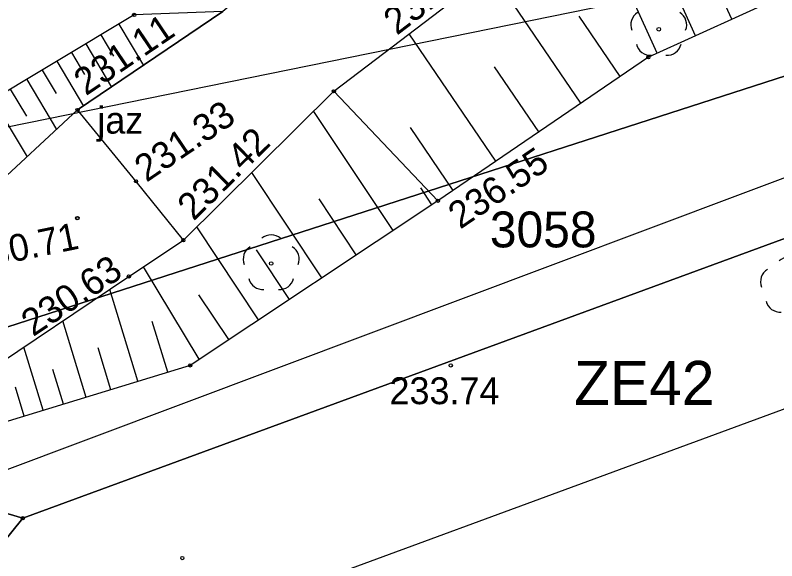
# Model space of a CAD drawing. Extents: x 6596400 to 6597200, y 5539751 to 5540251.
# Drawn here: x 6596752.84 to 6596774.08, y 5540046.04 to 5540061.24 of the extents above; entities that cross this region are included whole.
import ezdxf

# ---------------------------------------------------------------- set-up
doc = ezdxf.new("R2010")
doc.units = 0
for name, color, linetype in [('000 Inne (niezydentyfikowane)', 7, 'Continuous'), ('140-Punkty robocze', 7, 'Continuous'), ('203-punkt graniczny', 7, 'Continuous'), ('211-numer działki ewidencyjnej', 7, 'Continuous'), ('217-kontur klasyfikacyjny', 7, 'Continuous'), ('218-kontur użytku gruntowego', 7, 'Continuous'), ('219-działka ewidencyjna', 7, 'Continuous'), ('drzewo liściaste', 7, 'Continuous'), ('jaz', 7, 'Continuous'), ('jaz-Atr17', 7, 'Continuous'), ('Linia obszaru zagospodarowania terenu', 7, 'Continuous'), ('Opis obszaru zagospodarowania terenu', 7, 'Continuous'), ('pikieta sztuczna', 7, 'Continuous'), ('pikieta sztuczna-Atr2', 7, 'Continuous'), ('rów melioracyjny (poligon)', 7, 'Continuous'), ('skarpa nieumocniona', 7, 'Continuous'), ('skarpa umocniona', 7, 'Continuous'), ('Zakres', 7, 'Continuous')]:
    doc.layers.add(name, color=color, linetype=linetype)

# ---------------------------------------------------------------- blocks, each defined once
blk = doc.blocks.new('203')
blk.add_circle((0, 0), 0.045)
blk = doc.blocks.new('OP021')
blk.add_circle((0, 0), 0.05)
for centre, start, end in [((0, 0.4), 49.272, 130.728), ((-0.38, 0.124), 121.308, 202.548), ((0.38, 0.124), 337.452, 58.692), ((-0.235, -0.324), 193.221, 274.871), ((0.235, -0.324), 265.129, 346.779)]:
    blk.add_arc(centre, 0.4, start, end)
blk = doc.blocks.new('PIKIETA')
blk.add_circle((0, 0), 0.045)
blk = doc.blocks.new('PW01')
blk.add_circle((0, 0), 0.045)

msp = doc.modelspace()

# ---------------------------------------------------------------- linework, layer by layer
at = {"layer": '000 Inne (niezydentyfikowane)'}
for p, q in [((6596772.83, 5540061.13), (6596771.44, 5540064.19)), ((6596770.75, 5540060.18), (6596769.2, 5540063.59)), ((6596768.62, 5540058.79), (6596766.16, 5540062.4)), ((6596771.82, 5540060.67), (6596771.08, 5540062.29)), ((6596769.71, 5540059.53), (6596768.57, 5540061.21)), ((6596766.25, 5540057.17), (6596763.83, 5540060.72)), ((6596767.45, 5540057.99), (6596766.21, 5540059.8)), ((6596763.38, 5540055.24), (6596761.17, 5540058.56)), ((6596765.06, 5540056.36), (6596763.87, 5540058.11)), ((6596761.39, 5540053.92), (6596759.44, 5540056.86)), ((6596764.46, 5540055.96), (6596764.15, 5540056.43)), ((6596762.35, 5540054.56), (6596761.32, 5540056.12)), ((6596759.63, 5540052.75), (6596757.91, 5540055.34)), ((6596760.49, 5540053.32), (6596759.57, 5540054.7)), ((6596757.97, 5540051.65), (6596756.42, 5540054.23)), ((6596756.26, 5540051.04), (6596755.48, 5540053.6)), ((6596758.8, 5540052.2), (6596757.96, 5540053.45)), ((6596754.82, 5540050.59), (6596754.17, 5540052.72)), ((6596757.1, 5540051.29), (6596756.66, 5540052.7)), ((6596753.62, 5540050.23), (6596753.08, 5540051.99)), ((6596755.51, 5540050.8), (6596755.15, 5540051.97)), ((6596754.19, 5540050.4), (6596753.89, 5540051.37)), ((6596753.09, 5540050.07), (6596752.85, 5540050.87))]:
    msp.add_line(p, q, dxfattribs=at)
for points in [[(6596755.73, 5540060.99), (6596756.42, 5540059.84)], [(6596755.23, 5540060.69), (6596755.58, 5540060.1)], [(6596754.81, 5540060.44), (6596755.53, 5540059.24)], [(6596754.41, 5540060.2), (6596754.77, 5540059.59)], [(6596754, 5540059.96), (6596754.74, 5540058.71)], [(6596753.59, 5540059.71), (6596753.98, 5540059.06)], [(6596753.16, 5540059.45), (6596753.99, 5540058.06)], [(6596752.7, 5540059.18), (6596753.15, 5540058.43)], [(6596752.21, 5540058.89), (6596753.17, 5540057.29)]]:
    msp.add_lwpolyline(points, dxfattribs=at)
at = {"layer": '217-kontur klasyfikacyjny'}
for points in [[(6596787.06, 5540059.7), (6596753.05, 5540047.22)], [(6596753.05, 5540047.22), (6596750.47, 5540044.03)]]:
    msp.add_lwpolyline(points, dxfattribs=at)
at = {"layer": '218-kontur użytku gruntowego'}
for points in [[(6596786.08, 5540063.35), (6596749.37, 5540051.51)], [(6596749.37, 5540051.51), (6596786.08, 5540063.35)], [(6596787.06, 5540059.7), (6596753.05, 5540047.22)], [(6596753.05, 5540047.22), (6596787.06, 5540059.7)], [(6596732.94, 5540053.15), (6596753.05, 5540047.22)], [(6596753.05, 5540047.22), (6596732.94, 5540053.15)], [(6596753.05, 5540047.22), (6596750.47, 5540044.03)], [(6596750.47, 5540044.03), (6596753.05, 5540047.22)]]:
    msp.add_lwpolyline(points, dxfattribs=at)
at = {"layer": '219-działka ewidencyjna'}
for points in [[(6596749.37, 5540051.51), (6596786.08, 5540063.35)], [(6596753.05, 5540047.22), (6596787.06, 5540059.7)], [(6596753.05, 5540047.22), (6596732.94, 5540053.15)], [(6596750.47, 5540044.03), (6596753.05, 5540047.22)]]:
    msp.add_lwpolyline(points, dxfattribs=at)
at = {"layer": 'jaz'}
msp.add_lwpolyline([(6596757.53, 5540054.97), (6596756.21, 5540056.61), (6596754.58, 5540058.6)], dxfattribs=at)
at = {"layer": 'Linia obszaru zagospodarowania terenu'}
for points in [[(6596720.263, 5540058.387), (6596728.96, 5540057.84), (6596731.45, 5540057.76), (6596731.02, 5540064.64), (6596745.49, 5540064.58), (6596746.99, 5540056.99), (6596772.84, 5540062.25), (6596786.21, 5540064.83), (6596807.99, 5540057.58), (6596818.837, 5540049.192)], [(6596816.371, 5540045.853), (6596805.78, 5540054.39), (6596786.09, 5540061.13), (6596752.3, 5540048.46), (6596750.16, 5540045.43), (6596750.4, 5540037.69), (6596745.15, 5540037.73), (6596747.098, 5540030.366)]]:
    msp.add_lwpolyline(points, dxfattribs=at)
at = {"layer": 'rów melioracyjny (poligon)'}
for points in [[(6596820.208, 5540051.05), (6596817.24, 5540053.08), (6596812.31, 5540056.77), (6596808.36, 5540059.4), (6596802.55, 5540062.58), (6596795.13, 5540065.25), (6596788.99, 5540067.23), (6596782.3, 5540068.04), (6596775.52, 5540068.1), (6596768.51, 5540067.33), (6596764.82, 5540065.79), (6596761.35, 5540063.62), (6596758.63, 5540061.34), (6596754.58, 5540058.6), (6596752.07, 5540056.28), (6596746.75, 5540055.19), (6596741.65, 5540054.82), (6596742.01, 5540050.53), (6596747.46, 5540050.98), (6596751.88, 5540051.19), (6596756.01, 5540053.96), (6596757.53, 5540054.97), (6596761.73, 5540059.12)], [(6596761.73, 5540059.12), (6596765.87, 5540062.28), (6596769.5, 5540063.71), (6596775.27, 5540065.15), (6596782.49, 5540064.38), (6596788.18, 5540063.76), (6596793.92, 5540062.6), (6596807.97, 5540055.99), (6596815, 5540051.7), (6596818.611, 5540048.887)]]:
    msp.add_lwpolyline(points, dxfattribs=at)
at = {"layer": 'skarpa nieumocniona'}
for points in [[(6596756.16, 5540061.25), (6596751.77, 5540058.62), (6596746.79, 5540058.12), (6596745.06, 5540060.97), (6596743.75, 5540062.98), (6596744.34, 5540066.61), (6596742.94, 5540074), (6596740.68, 5540078.45), (6596741.68, 5540074.92), (6596743.25, 5540066.3), (6596742.47, 5540061.97), (6596741.65, 5540054.82), (6596746.75, 5540055.19), (6596752.07, 5540056.28), (6596754.58, 5540058.6), (6596758.63, 5540061.34)], [(6596756.16, 5540061.25), (6596751.77, 5540058.62), (6596746.79, 5540058.12), (6596745.06, 5540060.97), (6596743.75, 5540062.98), (6596744.34, 5540066.61), (6596742.94, 5540074), (6596740.68, 5540078.45), (6596741.68, 5540074.92), (6596743.25, 5540066.3), (6596742.47, 5540061.97), (6596741.65, 5540054.82), (6596746.75, 5540055.19), (6596752.07, 5540056.28), (6596754.58, 5540058.6), (6596758.63, 5540061.34)], [(6596764.63, 5540056.07), (6596757.72, 5540051.48), (6596748.68, 5540048.72), (6596744.91, 5540048.46), (6596747.72, 5540041.03), (6596748.61, 5540037.56), (6596751.13, 5540029.81), (6596749.69, 5540030.01), (6596747.71, 5540037.43), (6596746.88, 5540041.11), (6596746.88, 5540042.02), (6596743.2, 5540046.89), (6596742.01, 5540050.53), (6596747.46, 5540050.98), (6596751.88, 5540051.19), (6596756.01, 5540053.96), (6596757.53, 5540054.97), (6596761.73, 5540059.12)], [(6596764.63, 5540056.07), (6596757.72, 5540051.48), (6596748.68, 5540048.72), (6596744.91, 5540048.46), (6596747.72, 5540041.03), (6596748.61, 5540037.56), (6596751.13, 5540029.81), (6596749.69, 5540030.01), (6596747.71, 5540037.43), (6596746.88, 5540041.11), (6596746.88, 5540042.02), (6596743.2, 5540046.89), (6596742.01, 5540050.53), (6596747.46, 5540050.98), (6596751.88, 5540051.19), (6596756.01, 5540053.96), (6596757.53, 5540054.97), (6596761.73, 5540059.12)]]:
    msp.add_lwpolyline(points, close=True, dxfattribs=at)
at = {"layer": 'skarpa umocniona'}
msp.add_lwpolyline([(6596782.49, 5540064.38), (6596788.18, 5540063.76), (6596793.92, 5540062.6), (6596807.97, 5540055.99), (6596815, 5540051.7), (6596818.61, 5540048.89), (6596817.09, 5540046.82), (6596813.04, 5540049.86), (6596807.32, 5540053.71), (6596801, 5540055.88), (6596793.16, 5540059.3), (6596788.6, 5540060.8), (6596783.73, 5540060.81), (6596779.28, 5540061), (6596774.44, 5540061.86), (6596770.5, 5540060.07), (6596764.63, 5540056.07), (6596761.73, 5540059.12), (6596765.87, 5540062.28), (6596769.5, 5540063.71), (6596775.27, 5540065.15)], close=True, dxfattribs=at)
msp.add_lwpolyline([(6596782.49, 5540064.38), (6596788.18, 5540063.76), (6596793.92, 5540062.6), (6596807.97, 5540055.99), (6596815, 5540051.7), (6596818.61, 5540048.89), (6596817.09, 5540046.82), (6596813.04, 5540049.86), (6596807.32, 5540053.71), (6596801, 5540055.88), (6596793.16, 5540059.3), (6596788.6, 5540060.8), (6596783.73, 5540060.81), (6596779.28, 5540061), (6596774.44, 5540061.86), (6596770.5, 5540060.07), (6596764.63, 5540056.07), (6596761.73, 5540059.12), (6596765.87, 5540062.28), (6596769.5, 5540063.71), (6596775.27, 5540065.15)], close=True, dxfattribs=at)
at = {"layer": 'Zakres'}
msp.add_lwpolyline([(6596822.22, 5540097.5), (6596800.39, 5540105.4), (6596755.76, 5540121.45), (6596697.73, 5540120.74), (6596659.35, 5540133.92), (6596647.64, 5540109.28), (6596697.73, 5540077), (6596721.01, 5540057.77), (6596727.72, 5540045.95), (6596731.95, 5540033.61), (6596741.17, 5540031.18), (6596755.59, 5540029.2), (6596757.85, 5540044.22), (6596787.25, 5540055.04), (6596806.3, 5540048.33), (6596813.97, 5540042.6), (6596833.15, 5540068.58), (6596822.3, 5540077.75)], close=True, dxfattribs=at)

# ---------------------------------------------------------------- block references
at = {"layer": '140-Punkty robocze'}
for p in [(6596756.16, 5540061.25), (6596770.5, 5540060.07), (6596761.73, 5540059.12), (6596754.58, 5540058.6), (6596756.21, 5540056.61), (6596764.63, 5540056.07), (6596754.57, 5540055.58), (6596754.58, 5540055.59), (6596757.53, 5540054.97), (6596756.01, 5540053.96), (6596757.72, 5540051.48), (6596764.99, 5540051.48), (6596757.5, 5540046.11)]:
    msp.add_blockref('PIKIETA', p, dxfattribs=at)
at = {"layer": '203-punkt graniczny'}
msp.add_blockref('203', (6596753.05, 5540047.22), dxfattribs=at)
at = {"layer": 'drzewo liściaste'}
for p in [(6596770.79, 5540060.85), (6596759.98, 5540054.32), (6596774.41, 5540053.69)]:
    msp.add_blockref('OP021', p, dxfattribs=at)
at = {"layer": 'pikieta sztuczna'}
for p in [(6596754.58, 5540058.6), (6596756.21, 5540056.61), (6596764.63, 5540056.07), (6596754.58, 5540055.59), (6596757.53, 5540054.97), (6596756.01, 5540053.96), (6596764.99, 5540051.48), (6596757.5, 5540046.11)]:
    msp.add_blockref('PW01', p, dxfattribs=at)

# ---------------------------------------------------------------- texts
at = {"layer": '211-numer działki ewidencyjnej'}
msp.add_text('3058', height=1, dxfattribs=at).set_placement((6596766.08, 5540054.77))
at = {"layer": 'jaz-Atr17'}
msp.add_text('jaz', height=0.75, dxfattribs=at).set_placement((6596755.13, 5540057.94))
at = {"layer": 'Opis obszaru zagospodarowania terenu'}
msp.add_text('ZE42', height=1.225, dxfattribs=at).set_placement((6596768.43, 5540050.38))
at = {"layer": 'pikieta sztuczna-Atr2'}
for s, rotation, p in [('231.49', 37.354, (6596763.485, 5540060.664)), ('231.11', 34.08, (6596754.81, 5540058.979)), ('231.33', 34.08, (6596756.5, 5540056.569)), ('231.42', 44.657, (6596757.817, 5540055.487)), ('236.55', 34.272, (6596765.252, 5540055.26)), ('230.71', 11.579, (6596751.651, 5540054.125)), ('230.63', 33.85, (6596753.338, 5540052.267))]:
    msp.add_text(s, height=0.75, rotation=rotation, dxfattribs=at).set_placement(p)
msp.add_text('233.74', height=0.75, dxfattribs=at).set_placement((6596763.28, 5540050.4))

doc.saveas('drawing.dxf')
